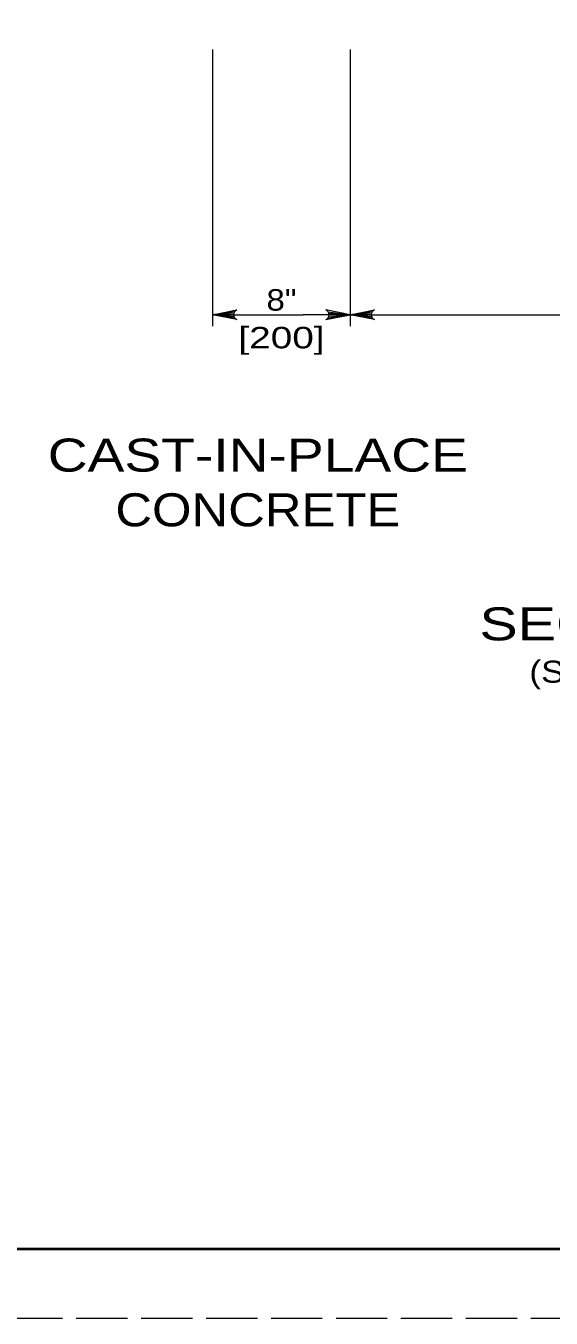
# Model space of a CAD drawing. Extents: x 1083.1 to 1117.1, y 719.4 to 763.4.
# Drawn here: x 1089.84 to 1093.66, y 719.35 to 728.74 of the extents above; entities that cross this region are included whole.
import ezdxf
from ezdxf.enums import TextEntityAlignment as Align

# ---------------------------------------------------------------- set-up
doc = ezdxf.new("R2010")
doc.units = 0
doc.header["$LTSCALE"] = 0.062
doc.linetypes.add('LONG_DASHED', pattern=[7.5, 6, -1.5])
doc.layers.add('1', color=7, linetype='Continuous', lineweight=13)

msp = doc.modelspace()

# ---------------------------------------------------------------- linework, layer by layer
at = {"layer": '1'}
for p, q in [((1091.19642, 728.56808), (1091.19642, 726.55892)), ((1092.19642, 728.56808), (1092.19642, 726.55892)), ((1091.35675, 726.66467), (1091.19642, 726.64225)), ((1091.35133, 726.65358), (1091.19642, 726.64225)), ((1091.19642, 726.64225), (1091.85575, 726.64225)), ((1091.34967, 726.64225), (1091.19642, 726.64225)), ((1091.3525, 726.62783), (1091.19642, 726.64225)), ((1091.35867, 726.6175), (1091.19642, 726.64225)), ((1092.19642, 726.64225), (1091.85575, 726.64225)), ((1092.03417, 726.6175), (1092.19642, 726.64225)), ((1092.03608, 726.66467), (1092.19642, 726.64225)), ((1092.04033, 726.62783), (1092.19642, 726.64225)), ((1092.0415, 726.65358), (1092.19642, 726.64225)), ((1092.04317, 726.64225), (1092.19642, 726.64225)), ((1092.35675, 726.66467), (1092.19642, 726.64225)), ((1092.35125, 726.65358), (1092.19642, 726.64225)), ((1092.19642, 726.64225), (1094.55033, 726.64225)), ((1092.34967, 726.64225), (1092.19642, 726.64225)), ((1092.3525, 726.62783), (1092.19642, 726.64225)), ((1092.35858, 726.6175), (1092.19642, 726.64225))]:
    msp.add_line(p, q, dxfattribs=at)
at = {"layer": '1', "linetype": 'LONG_DASHED'}
msp.add_lwpolyline([(1083.12642, 719.35408), (1117.12642, 719.35408), (1117.12642, 741.35408), (1083.12642, 741.35408)], close=True, dxfattribs=at)
at = {"layer": '1', "lineweight": 25}
msp.add_lwpolyline([(1116.62642, 719.85408), (1085.12642, 719.85408), (1085.12642, 740.85408)], dxfattribs=at)
at = {"layer": '1', "lineweight": 40}
msp.add_lwpolyline([(1085.12642, 740.85408), (1116.62642, 740.85408), (1116.62642, 719.85408), (1085.12642, 719.85408)], close=True, dxfattribs=at)
msp.add_lwpolyline([(1085.12642, 740.85408), (1116.62642, 740.85408), (1116.62642, 719.85408), (1085.12642, 719.85408)], close=True, dxfattribs=at)
at = {"layer": '1'}
for points in [[(1091.3735, 726.60683), (1091.19642, 726.64225), (1091.3735, 726.67767)], [(1092.01933, 726.60683), (1092.19642, 726.64225), (1092.01933, 726.67767)], [(1092.3735, 726.60683), (1092.19642, 726.64225), (1092.3735, 726.67767)]]:
    msp.add_lwpolyline(points, dxfattribs=at)
for centre, start, end in [((1091.38782, 726.64231), 112.08782, 247.91395), ((1092.00502, 726.64231), 292.08605, 67.91218), ((1092.38777, 726.64231), 112.08782, 247.91395)]:
    msp.add_arc(centre, 0.03822, start, end, dxfattribs=at)

# ---------------------------------------------------------------- texts
for s, height, width, p in [('8"', 0.156, 1.15, (1091.69792, 726.67233)), ('[200]', 0.156, 1.35, (1091.69792, 726.39825)), ('CAST-IN-PLACE', 0.24, 1.25, (1091.52596, 725.50283)), ('CONCRETE', 0.24, 1.15, (1091.52592, 725.10542))]:
    msp.add_text(s, height=height, dxfattribs=dict(at, width=width)).set_placement(p, align=Align.CENTER)
for s, height, width, p in [('SECTION A-A', 0.24, 1.3, (1093.13642, 724.27708)), ('(See Sht. 1/2.)', 0.16, 1.2, (1093.49883, 723.96983))]:
    msp.add_text(s, height=height, dxfattribs=dict(at, width=width)).set_placement(p)

doc.saveas('drawing.dxf')
